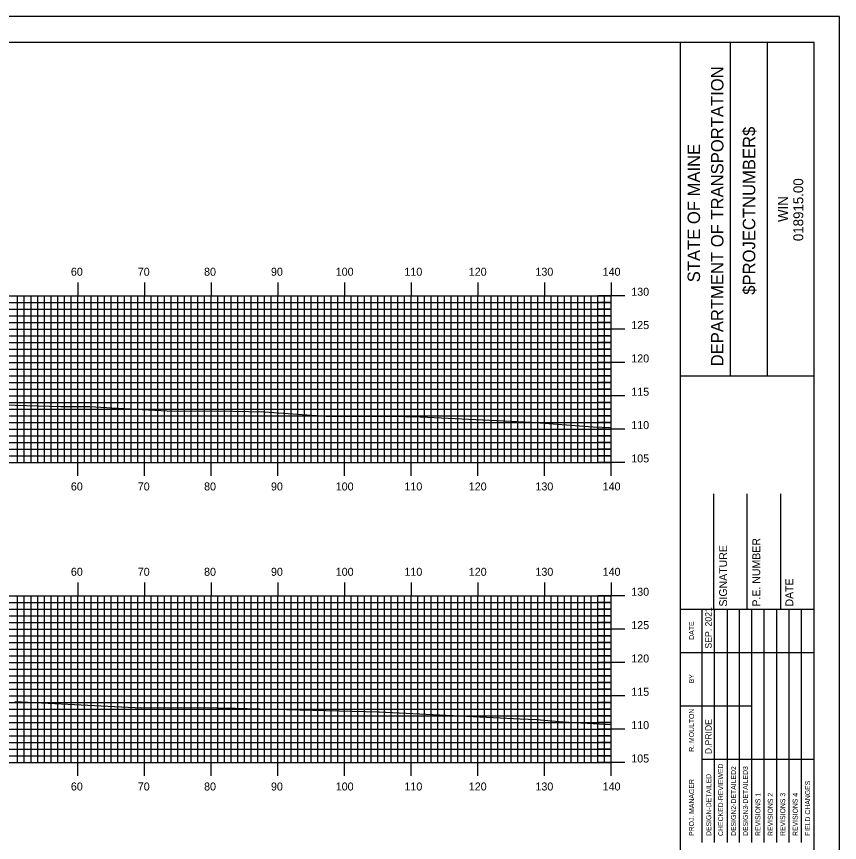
# Model space of a CAD drawing. Extents: x 1772022 to 1772366, y 442591 to 442811.
# Drawn here: x 1772238.9 to 1772362.3, y 442686.7 to 442810.5 of the extents above; entities that cross this region are included whole.
import ezdxf

# ---------------------------------------------------------------- set-up
doc = ezdxf.new("R2010")
doc.units = 0
for name, color, linetype in [('BORDER', 7, 'Continuous'), ('H_V ANNOTATION', 7, 'Continuous'), ('MAJOR', 7, 'Continuous'), ('MINOR', 7, 'Continuous'), ('PLOT BOUNDARY', 7, 'Continuous'), ('S_Roadway_Centerline', 7, 'Continuous')]:
    doc.layers.add(name, color=color, linetype=linetype)

msp = doc.modelspace()

# ---------------------------------------------------------------- linework, layer by layer
at = {"layer": 'BORDER'}
for p, q in [((1772338.49, 442596.67), (1772338.49, 442806.67)), ((1772345.95, 442756.66), (1772345.95, 442806.66)), ((1772351.54, 442756.66), (1772351.54, 442806.66)), ((1772338.5, 442756.65), (1772358.49, 442756.65)), ((1772343.49, 442721.67), (1772343.49, 442738.97)), ((1772348.49, 442721.67), (1772348.49, 442738.97)), ((1772353.49, 442721.67), (1772353.49, 442738.97)), ((1772338.49, 442721.67), (1772358.49, 442721.67))]:
    msp.add_line(p, q, dxfattribs=at)
msp.add_lwpolyline([(1772038.49, 442596.67), (1772358.49, 442596.67), (1772358.49, 442806.67), (1772038.49, 442806.67)], close=True, dxfattribs=at)
for points in [[(1772341.72, 442715.17), (1772341.72, 442721.67)], [(1772343.59, 442686.68), (1772343.59, 442721.67)], [(1772345.45, 442721.67), (1772345.45, 442686.68)], [(1772347.32, 442686.68), (1772347.32, 442721.67)], [(1772349.18, 442686.68), (1772349.18, 442721.67)], [(1772351.04, 442686.68), (1772351.04, 442721.67)], [(1772352.91, 442686.68), (1772352.91, 442721.67)], [(1772354.77, 442686.68), (1772354.77, 442721.67)], [(1772356.63, 442686.68), (1772356.63, 442721.67)], [(1772341.73, 442686.68), (1772341.73, 442720.26)], [(1772338.49, 442715.17), (1772358.49, 442715.17)], [(1772338.49, 442707.17), (1772341.73, 442707.17)], [(1772341.72, 442707.17), (1772349.18, 442707.17)], [(1772341.72, 442699.17), (1772358.49, 442699.17)]]:
    msp.add_lwpolyline(points, dxfattribs=at)
at = {"layer": 'MAJOR'}
for p, q in [((1772248.09, 442770.67), (1772248.09, 442768.67)), ((1772258.09, 442770.67), (1772258.09, 442768.67)), ((1772268.09, 442770.67), (1772268.09, 442768.67)), ((1772278.09, 442770.67), (1772278.09, 442768.67)), ((1772288.09, 442770.67), (1772288.09, 442768.67)), ((1772298.09, 442770.67), (1772298.09, 442768.67)), ((1772308.09, 442770.67), (1772308.09, 442768.67)), ((1772318.09, 442770.67), (1772318.09, 442768.67)), ((1772328.09, 442770.67), (1772328.09, 442768.67)), ((1772048.09, 442768.67), (1772328.09, 442768.67)), ((1772048.09, 442768.67), (1772328.09, 442768.67)), ((1772248.09, 442743.67), (1772248.09, 442768.67)), ((1772258.09, 442743.67), (1772258.09, 442768.67)), ((1772268.09, 442743.67), (1772268.09, 442768.67)), ((1772278.09, 442743.67), (1772278.09, 442768.67)), ((1772288.09, 442743.67), (1772288.09, 442768.67)), ((1772298.09, 442743.67), (1772298.09, 442768.67)), ((1772308.09, 442743.67), (1772308.09, 442768.67)), ((1772318.09, 442743.67), (1772318.09, 442768.67)), ((1772330.1, 442768.67), (1772326.09, 442768.67)), ((1772328.09, 442743.67), (1772328.09, 442768.67)), ((1772328.09, 442743.67), (1772328.09, 442768.67)), ((1772048.09, 442763.67), (1772328.09, 442763.67)), ((1772330.1, 442763.67), (1772326.09, 442763.67)), ((1772048.09, 442758.67), (1772328.09, 442758.67)), ((1772330.1, 442758.67), (1772326.09, 442758.67)), ((1772048.09, 442753.67), (1772328.09, 442753.67)), ((1772330.1, 442753.67), (1772326.09, 442753.67)), ((1772048.09, 442748.67), (1772328.09, 442748.67)), ((1772330.1, 442748.67), (1772326.09, 442748.67)), ((1772048.09, 442743.67), (1772328.09, 442743.67)), ((1772048.09, 442743.67), (1772328.09, 442743.67)), ((1772248.09, 442741.66), (1772248.09, 442743.67)), ((1772258.09, 442741.66), (1772258.09, 442743.67)), ((1772268.09, 442741.66), (1772268.09, 442743.67)), ((1772278.09, 442741.66), (1772278.09, 442743.67)), ((1772288.09, 442741.66), (1772288.09, 442743.67)), ((1772298.09, 442741.66), (1772298.09, 442743.67)), ((1772308.09, 442741.66), (1772308.09, 442743.67)), ((1772318.09, 442741.66), (1772318.09, 442743.67)), ((1772330.1, 442743.67), (1772326.09, 442743.67)), ((1772328.09, 442741.66), (1772328.09, 442743.67)), ((1772248.09, 442725.67), (1772248.09, 442723.67)), ((1772258.09, 442725.67), (1772258.09, 442723.67)), ((1772268.09, 442725.67), (1772268.09, 442723.67)), ((1772278.09, 442725.67), (1772278.09, 442723.67)), ((1772288.09, 442725.67), (1772288.09, 442723.67)), ((1772298.09, 442725.67), (1772298.09, 442723.67)), ((1772308.09, 442725.67), (1772308.09, 442723.67)), ((1772318.09, 442725.67), (1772318.09, 442723.67)), ((1772328.09, 442725.67), (1772328.09, 442723.67)), ((1772048.09, 442723.67), (1772328.09, 442723.67)), ((1772048.09, 442723.67), (1772328.09, 442723.67)), ((1772248.09, 442698.67), (1772248.09, 442723.67)), ((1772258.09, 442698.67), (1772258.09, 442723.67)), ((1772268.09, 442698.67), (1772268.09, 442723.67)), ((1772278.09, 442698.67), (1772278.09, 442723.67)), ((1772288.09, 442698.67), (1772288.09, 442723.67)), ((1772298.09, 442698.67), (1772298.09, 442723.67)), ((1772308.09, 442698.67), (1772308.09, 442723.67)), ((1772318.09, 442698.67), (1772318.09, 442723.67)), ((1772330.1, 442723.67), (1772326.09, 442723.67)), ((1772328.09, 442698.67), (1772328.09, 442723.67)), ((1772328.09, 442698.67), (1772328.09, 442723.67)), ((1772048.09, 442718.67), (1772328.09, 442718.67)), ((1772330.1, 442718.67), (1772326.09, 442718.67)), ((1772048.09, 442713.67), (1772328.09, 442713.67)), ((1772330.1, 442713.67), (1772326.09, 442713.67)), ((1772048.09, 442708.67), (1772328.09, 442708.67)), ((1772330.1, 442708.67), (1772326.09, 442708.67)), ((1772048.09, 442703.67), (1772328.09, 442703.67)), ((1772330.1, 442703.67), (1772326.09, 442703.67)), ((1772048.09, 442698.67), (1772328.09, 442698.67)), ((1772048.09, 442698.67), (1772328.09, 442698.67)), ((1772248.09, 442696.66), (1772248.09, 442698.67)), ((1772258.09, 442696.66), (1772258.09, 442698.67)), ((1772268.09, 442696.66), (1772268.09, 442698.67)), ((1772278.09, 442696.66), (1772278.09, 442698.67)), ((1772288.09, 442696.66), (1772288.09, 442698.67)), ((1772298.09, 442696.66), (1772298.09, 442698.67)), ((1772308.09, 442696.66), (1772308.09, 442698.67)), ((1772318.09, 442696.66), (1772318.09, 442698.67)), ((1772330.1, 442698.67), (1772326.09, 442698.67)), ((1772328.09, 442696.66), (1772328.09, 442698.67))]:
    msp.add_line(p, q, dxfattribs=at)
at = {"layer": 'MINOR'}
for p, q in [((1772239.09, 442743.67), (1772239.09, 442768.67)), ((1772240.09, 442743.67), (1772240.09, 442768.67)), ((1772241.09, 442743.67), (1772241.09, 442768.67)), ((1772242.09, 442743.67), (1772242.09, 442768.67)), ((1772243.09, 442743.67), (1772243.09, 442768.67)), ((1772244.09, 442743.67), (1772244.09, 442768.67)), ((1772245.09, 442743.67), (1772245.09, 442768.67)), ((1772246.09, 442743.67), (1772246.09, 442768.67)), ((1772247.09, 442743.67), (1772247.09, 442768.67)), ((1772249.09, 442743.67), (1772249.09, 442768.67)), ((1772250.09, 442743.67), (1772250.09, 442768.67)), ((1772251.09, 442743.67), (1772251.09, 442768.67)), ((1772252.09, 442743.67), (1772252.09, 442768.67)), ((1772253.09, 442743.67), (1772253.09, 442768.67)), ((1772254.09, 442743.67), (1772254.09, 442768.67)), ((1772255.09, 442743.67), (1772255.09, 442768.67)), ((1772256.09, 442743.67), (1772256.09, 442768.67)), ((1772257.09, 442743.67), (1772257.09, 442768.67)), ((1772259.09, 442743.67), (1772259.09, 442768.67)), ((1772260.09, 442743.67), (1772260.09, 442768.67)), ((1772261.09, 442743.67), (1772261.09, 442768.67)), ((1772262.09, 442743.67), (1772262.09, 442768.67)), ((1772263.09, 442743.67), (1772263.09, 442768.67)), ((1772264.09, 442743.67), (1772264.09, 442768.67)), ((1772265.09, 442743.67), (1772265.09, 442768.67)), ((1772266.09, 442743.67), (1772266.09, 442768.67)), ((1772267.09, 442743.67), (1772267.09, 442768.67)), ((1772269.09, 442743.67), (1772269.09, 442768.67)), ((1772270.09, 442743.67), (1772270.09, 442768.67)), ((1772271.09, 442743.67), (1772271.09, 442768.67)), ((1772272.09, 442743.67), (1772272.09, 442768.67)), ((1772273.09, 442743.67), (1772273.09, 442768.67)), ((1772274.09, 442743.67), (1772274.09, 442768.67)), ((1772275.09, 442743.67), (1772275.09, 442768.67)), ((1772276.09, 442743.67), (1772276.09, 442768.67)), ((1772277.09, 442743.67), (1772277.09, 442768.67)), ((1772279.09, 442743.67), (1772279.09, 442768.67)), ((1772280.09, 442743.67), (1772280.09, 442768.67)), ((1772281.09, 442743.67), (1772281.09, 442768.67)), ((1772282.09, 442743.67), (1772282.09, 442768.67)), ((1772283.09, 442743.67), (1772283.09, 442768.67)), ((1772284.09, 442743.67), (1772284.09, 442768.67)), ((1772285.09, 442743.67), (1772285.09, 442768.67)), ((1772286.09, 442743.67), (1772286.09, 442768.67)), ((1772287.09, 442743.67), (1772287.09, 442768.67)), ((1772289.09, 442743.67), (1772289.09, 442768.67)), ((1772290.09, 442743.67), (1772290.09, 442768.67)), ((1772291.09, 442743.67), (1772291.09, 442768.67)), ((1772292.09, 442743.67), (1772292.09, 442768.67)), ((1772293.09, 442743.67), (1772293.09, 442768.67)), ((1772294.09, 442743.67), (1772294.09, 442768.67)), ((1772295.09, 442743.67), (1772295.09, 442768.67)), ((1772296.09, 442743.67), (1772296.09, 442768.67)), ((1772297.09, 442743.67), (1772297.09, 442768.67)), ((1772299.09, 442743.67), (1772299.09, 442768.67)), ((1772300.09, 442743.67), (1772300.09, 442768.67)), ((1772301.09, 442743.67), (1772301.09, 442768.67)), ((1772302.09, 442743.67), (1772302.09, 442768.67)), ((1772303.09, 442743.67), (1772303.09, 442768.67)), ((1772304.09, 442743.67), (1772304.09, 442768.67)), ((1772305.09, 442743.67), (1772305.09, 442768.67)), ((1772306.09, 442743.67), (1772306.09, 442768.67)), ((1772307.09, 442743.67), (1772307.09, 442768.67)), ((1772309.09, 442743.67), (1772309.09, 442768.67)), ((1772310.09, 442743.67), (1772310.09, 442768.67)), ((1772311.09, 442743.67), (1772311.09, 442768.67)), ((1772312.09, 442743.67), (1772312.09, 442768.67)), ((1772313.09, 442743.67), (1772313.09, 442768.67)), ((1772314.09, 442743.67), (1772314.09, 442768.67)), ((1772315.09, 442743.67), (1772315.09, 442768.67)), ((1772316.09, 442743.67), (1772316.09, 442768.67)), ((1772317.09, 442743.67), (1772317.09, 442768.67)), ((1772319.09, 442743.67), (1772319.09, 442768.67)), ((1772320.09, 442743.67), (1772320.09, 442768.67)), ((1772321.09, 442743.67), (1772321.09, 442768.67)), ((1772322.09, 442743.67), (1772322.09, 442768.67)), ((1772323.09, 442743.67), (1772323.09, 442768.67)), ((1772324.09, 442743.67), (1772324.09, 442768.67)), ((1772325.09, 442743.67), (1772325.09, 442768.67)), ((1772326.09, 442743.67), (1772326.09, 442768.67)), ((1772327.09, 442743.67), (1772327.09, 442768.67)), ((1772048.09, 442767.67), (1772328.09, 442767.67)), ((1772328.09, 442767.67), (1772326.09, 442767.67)), ((1772048.09, 442766.67), (1772328.09, 442766.67)), ((1772328.09, 442766.67), (1772326.09, 442766.67)), ((1772048.09, 442765.67), (1772328.09, 442765.67)), ((1772328.09, 442765.67), (1772326.09, 442765.67)), ((1772048.09, 442764.67), (1772328.09, 442764.67)), ((1772328.09, 442764.67), (1772326.09, 442764.67)), ((1772048.09, 442762.67), (1772328.09, 442762.67)), ((1772328.09, 442762.67), (1772326.09, 442762.67)), ((1772048.09, 442761.67), (1772328.09, 442761.67)), ((1772328.09, 442761.67), (1772326.09, 442761.67)), ((1772048.09, 442760.67), (1772328.09, 442760.67)), ((1772328.09, 442760.67), (1772326.09, 442760.67)), ((1772048.09, 442759.67), (1772328.09, 442759.67)), ((1772328.09, 442759.67), (1772326.09, 442759.67)), ((1772048.09, 442757.67), (1772328.09, 442757.67)), ((1772328.09, 442757.67), (1772326.09, 442757.67)), ((1772048.09, 442756.67), (1772328.09, 442756.67)), ((1772328.09, 442756.67), (1772326.09, 442756.67)), ((1772048.09, 442755.67), (1772328.09, 442755.67)), ((1772328.09, 442755.67), (1772326.09, 442755.67)), ((1772048.09, 442754.67), (1772328.09, 442754.67)), ((1772328.09, 442754.67), (1772326.09, 442754.67)), ((1772048.09, 442752.67), (1772328.09, 442752.67)), ((1772328.09, 442752.67), (1772326.09, 442752.67)), ((1772048.09, 442751.67), (1772328.09, 442751.67)), ((1772328.09, 442751.67), (1772326.09, 442751.67)), ((1772048.09, 442750.67), (1772328.09, 442750.67)), ((1772328.09, 442750.67), (1772326.09, 442750.67)), ((1772048.09, 442749.67), (1772328.09, 442749.67)), ((1772328.09, 442749.67), (1772326.09, 442749.67)), ((1772048.09, 442747.67), (1772328.09, 442747.67)), ((1772328.09, 442747.67), (1772326.09, 442747.67)), ((1772048.09, 442746.67), (1772328.09, 442746.67)), ((1772328.09, 442746.67), (1772326.09, 442746.67)), ((1772048.09, 442745.67), (1772328.09, 442745.67)), ((1772328.09, 442745.67), (1772326.09, 442745.67)), ((1772048.09, 442744.67), (1772328.09, 442744.67)), ((1772328.09, 442744.67), (1772326.09, 442744.67)), ((1772239.09, 442698.67), (1772239.09, 442723.67)), ((1772240.09, 442698.67), (1772240.09, 442723.67)), ((1772241.09, 442698.67), (1772241.09, 442723.67)), ((1772242.09, 442698.67), (1772242.09, 442723.67)), ((1772243.09, 442698.67), (1772243.09, 442723.67)), ((1772244.09, 442698.67), (1772244.09, 442723.67)), ((1772245.09, 442698.67), (1772245.09, 442723.67)), ((1772246.09, 442698.67), (1772246.09, 442723.67)), ((1772247.09, 442698.67), (1772247.09, 442723.67)), ((1772249.09, 442698.67), (1772249.09, 442723.67)), ((1772250.09, 442698.67), (1772250.09, 442723.67)), ((1772251.09, 442698.67), (1772251.09, 442723.67)), ((1772252.09, 442698.67), (1772252.09, 442723.67)), ((1772253.09, 442698.67), (1772253.09, 442723.67)), ((1772254.09, 442698.67), (1772254.09, 442723.67)), ((1772255.09, 442698.67), (1772255.09, 442723.67)), ((1772256.09, 442698.67), (1772256.09, 442723.67)), ((1772257.09, 442698.67), (1772257.09, 442723.67)), ((1772259.09, 442698.67), (1772259.09, 442723.67)), ((1772260.09, 442698.67), (1772260.09, 442723.67)), ((1772261.09, 442698.67), (1772261.09, 442723.67)), ((1772262.09, 442698.67), (1772262.09, 442723.67)), ((1772263.09, 442698.67), (1772263.09, 442723.67)), ((1772264.09, 442698.67), (1772264.09, 442723.67)), ((1772265.09, 442698.67), (1772265.09, 442723.67)), ((1772266.09, 442698.67), (1772266.09, 442723.67)), ((1772267.09, 442698.67), (1772267.09, 442723.67)), ((1772269.09, 442698.67), (1772269.09, 442723.67)), ((1772270.09, 442698.67), (1772270.09, 442723.67)), ((1772271.09, 442698.67), (1772271.09, 442723.67)), ((1772272.09, 442698.67), (1772272.09, 442723.67)), ((1772273.09, 442698.67), (1772273.09, 442723.67)), ((1772274.09, 442698.67), (1772274.09, 442723.67)), ((1772275.09, 442698.67), (1772275.09, 442723.67)), ((1772276.09, 442698.67), (1772276.09, 442723.67)), ((1772277.09, 442698.67), (1772277.09, 442723.67)), ((1772279.09, 442698.67), (1772279.09, 442723.67)), ((1772280.09, 442698.67), (1772280.09, 442723.67)), ((1772281.09, 442698.67), (1772281.09, 442723.67)), ((1772282.09, 442698.67), (1772282.09, 442723.67)), ((1772283.09, 442698.67), (1772283.09, 442723.67)), ((1772284.09, 442698.67), (1772284.09, 442723.67)), ((1772285.09, 442698.67), (1772285.09, 442723.67)), ((1772286.09, 442698.67), (1772286.09, 442723.67)), ((1772287.09, 442698.67), (1772287.09, 442723.67)), ((1772289.09, 442698.67), (1772289.09, 442723.67)), ((1772290.09, 442698.67), (1772290.09, 442723.67)), ((1772291.09, 442698.67), (1772291.09, 442723.67)), ((1772292.09, 442698.67), (1772292.09, 442723.67)), ((1772293.09, 442698.67), (1772293.09, 442723.67)), ((1772294.09, 442698.67), (1772294.09, 442723.67)), ((1772295.09, 442698.67), (1772295.09, 442723.67)), ((1772296.09, 442698.67), (1772296.09, 442723.67)), ((1772297.09, 442698.67), (1772297.09, 442723.67)), ((1772299.09, 442698.67), (1772299.09, 442723.67)), ((1772300.09, 442698.67), (1772300.09, 442723.67)), ((1772301.09, 442698.67), (1772301.09, 442723.67)), ((1772302.09, 442698.67), (1772302.09, 442723.67)), ((1772303.09, 442698.67), (1772303.09, 442723.67)), ((1772304.09, 442698.67), (1772304.09, 442723.67)), ((1772305.09, 442698.67), (1772305.09, 442723.67)), ((1772306.09, 442698.67), (1772306.09, 442723.67)), ((1772307.09, 442698.67), (1772307.09, 442723.67)), ((1772309.09, 442698.67), (1772309.09, 442723.67)), ((1772310.09, 442698.67), (1772310.09, 442723.67)), ((1772311.09, 442698.67), (1772311.09, 442723.67)), ((1772312.09, 442698.67), (1772312.09, 442723.67)), ((1772313.09, 442698.67), (1772313.09, 442723.67)), ((1772314.09, 442698.67), (1772314.09, 442723.67)), ((1772315.09, 442698.67), (1772315.09, 442723.67)), ((1772316.09, 442698.67), (1772316.09, 442723.67)), ((1772317.09, 442698.67), (1772317.09, 442723.67)), ((1772319.09, 442698.67), (1772319.09, 442723.67)), ((1772320.09, 442698.67), (1772320.09, 442723.67)), ((1772321.09, 442698.67), (1772321.09, 442723.67)), ((1772322.09, 442698.67), (1772322.09, 442723.67)), ((1772323.09, 442698.67), (1772323.09, 442723.67)), ((1772324.09, 442698.67), (1772324.09, 442723.67)), ((1772325.09, 442698.67), (1772325.09, 442723.67)), ((1772326.09, 442698.67), (1772326.09, 442723.67)), ((1772327.09, 442698.67), (1772327.09, 442723.67)), ((1772048.09, 442722.67), (1772328.09, 442722.67)), ((1772048.09, 442721.67), (1772328.09, 442721.67)), ((1772328.09, 442722.67), (1772326.09, 442722.67)), ((1772328.09, 442721.67), (1772326.09, 442721.67)), ((1772048.09, 442720.67), (1772328.09, 442720.67)), ((1772328.09, 442720.67), (1772326.09, 442720.67)), ((1772048.09, 442719.67), (1772328.09, 442719.67)), ((1772328.09, 442719.67), (1772326.09, 442719.67)), ((1772048.09, 442717.67), (1772328.09, 442717.67)), ((1772048.09, 442716.67), (1772328.09, 442716.67)), ((1772328.09, 442717.67), (1772326.09, 442717.67)), ((1772328.09, 442716.67), (1772326.09, 442716.67)), ((1772048.09, 442715.67), (1772328.09, 442715.67)), ((1772328.09, 442715.67), (1772326.09, 442715.67)), ((1772048.09, 442714.67), (1772328.09, 442714.67)), ((1772328.09, 442714.67), (1772326.09, 442714.67)), ((1772048.09, 442712.67), (1772328.09, 442712.67)), ((1772048.09, 442711.67), (1772328.09, 442711.67)), ((1772328.09, 442712.67), (1772326.09, 442712.67)), ((1772328.09, 442711.67), (1772326.09, 442711.67)), ((1772048.09, 442710.67), (1772328.09, 442710.67)), ((1772328.09, 442710.67), (1772326.09, 442710.67)), ((1772048.09, 442709.67), (1772328.09, 442709.67)), ((1772328.09, 442709.67), (1772326.09, 442709.67)), ((1772048.09, 442707.67), (1772328.09, 442707.67)), ((1772048.09, 442706.67), (1772328.09, 442706.67)), ((1772328.09, 442707.67), (1772326.09, 442707.67)), ((1772328.09, 442706.67), (1772326.09, 442706.67)), ((1772048.09, 442705.67), (1772328.09, 442705.67)), ((1772328.09, 442705.67), (1772326.09, 442705.67)), ((1772048.09, 442704.67), (1772328.09, 442704.67)), ((1772328.09, 442704.67), (1772326.09, 442704.67)), ((1772048.09, 442702.67), (1772328.09, 442702.67)), ((1772048.09, 442701.67), (1772328.09, 442701.67)), ((1772328.09, 442702.67), (1772326.09, 442702.67)), ((1772328.09, 442701.67), (1772326.09, 442701.67)), ((1772048.09, 442700.67), (1772328.09, 442700.67)), ((1772328.09, 442700.67), (1772326.09, 442700.67)), ((1772048.09, 442699.67), (1772328.09, 442699.67)), ((1772328.09, 442699.67), (1772326.09, 442699.67))]:
    msp.add_line(p, q, dxfattribs=at)
at = {"layer": 'PLOT BOUNDARY'}
msp.add_lwpolyline([(1772022.31, 442590.55), (1772362.31, 442590.55), (1772362.31, 442810.55), (1772022.31, 442810.55)], close=True, dxfattribs=at)
at = {"layer": 'S_Roadway_Centerline'}
for points in [[(1772233.53, 442752.41), (1772245.56, 442752.05), (1772249.9, 442752.08), (1772254.06, 442751.82), (1772261.53, 442751.42), (1772271.36, 442751.35), (1772276.11, 442751.24), (1772285.3, 442750.63), (1772295.07, 442750.62), (1772299.5, 442750.5), (1772316.06, 442749.71), (1772325.32, 442749.02), (1772328.09, 442748.89)], [(1772238.68, 442707.82), (1772252.59, 442707.13), (1772257.72, 442706.89), (1772266.16, 442706.92), (1772271.73, 442706.82), (1772273.48, 442706.78), (1772293.2, 442706.28), (1772293.27, 442706.28), (1772293.28, 442706.28), (1772293.29, 442706.28), (1772314.43, 442705.2), (1772316.94, 442705.14), (1772320.84, 442704.79), (1772328.09, 442704.36)]]:
    msp.add_lwpolyline(points, dxfattribs=at)

# ---------------------------------------------------------------- texts
at = {"layer": 'BORDER'}
for s, height, p in [('DEPARTMENT OF TRANSPORTATION', 1.8635, (1772344.91, 442758.08)), ('$PROJECTNUMBER$', 1.8635, (1772349.68, 442768.82)), ('STATE OF MAINE', 1.8635, (1772341.4, 442770.69)), ('018915.00', 1.491, (1772356.88, 442776.86)), ('WIN', 1.491, (1772354.57, 442779.73)), ('P.E. NUMBER', 1.1811, (1772350.42, 442722.06)), ('SIGNATURE', 1.181, (1772345.45, 442722.06)), ('DATE', 1.181, (1772355.38, 442722.06)), ('SEP. 2021', 0.969, (1772343.14, 442715.76)), ('DATE', 0.743, (1772340.5, 442717.08)), ('BY', 0.743, (1772340.5, 442710.54)), ('R. MOULTON', 0.745, (1772340.5, 442700.28)), ('D.PRIDE', 0.969, (1772343.14, 442699.92)), ('CHECKED-REVIEWED', 0.7455, (1772344.86, 442687.65)), ('DESIGN2-DETAILED2', 0.7455, (1772346.79, 442687.65)), ('DESIGN3-DETAILED3', 0.7455, (1772348.58, 442687.65)), ('PROJ. MANAGER', 0.7455, (1772340.5, 442687.65)), ('DESIGN-DETAILED', 0.7455, (1772343.07, 442687.65)), ('FIELD CHANGES', 0.7455, (1772357.9, 442687.65)), ('REVISIONS 1', 0.7455, (1772350.45, 442687.65)), ('REVISIONS 2', 0.7455, (1772352.31, 442687.65)), ('REVISIONS 3', 0.7455, (1772354.17, 442687.65)), ('REVISIONS 4', 0.7455, (1772356.04, 442687.65))]:
    msp.add_text(s, height=height, rotation=90, dxfattribs=at).set_placement(p)
at = {"layer": 'H_V ANNOTATION'}
for s, p in [('60', (1772247.07, 442771.67)), ('70', (1772257.1, 442771.67)), ('80', (1772267.04, 442771.67)), ('90', (1772277.07, 442771.67)), ('100', (1772286.78, 442771.67)), ('110', (1772297.08, 442771.67)), ('120', (1772306.73, 442771.67)), ('130', (1772316.72, 442771.67)), ('140', (1772326.8, 442771.67)), ('130', (1772331.09, 442768.67)), ('125', (1772331.09, 442763.67)), ('120', (1772331.09, 442758.67)), ('115', (1772331.09, 442753.67)), ('110', (1772331.09, 442748.67)), ('105', (1772331.09, 442743.67)), ('60', (1772247.07, 442739.47)), ('70', (1772257.1, 442739.47)), ('80', (1772267.04, 442739.47)), ('90', (1772277.07, 442739.47)), ('100', (1772286.78, 442739.47)), ('110', (1772297.08, 442739.47)), ('120', (1772306.73, 442739.47)), ('130', (1772316.72, 442739.47)), ('140', (1772326.8, 442739.47)), ('60', (1772247.07, 442726.67)), ('70', (1772257.1, 442726.67)), ('80', (1772267.04, 442726.67)), ('90', (1772277.07, 442726.67)), ('100', (1772286.78, 442726.67)), ('110', (1772297.08, 442726.67)), ('120', (1772306.73, 442726.67)), ('130', (1772316.72, 442726.67)), ('140', (1772326.8, 442726.67)), ('130', (1772331.09, 442723.67)), ('125', (1772331.09, 442718.67)), ('120', (1772331.09, 442713.67)), ('115', (1772331.09, 442708.67)), ('110', (1772331.09, 442703.67)), ('105', (1772331.09, 442698.67)), ('60', (1772247.07, 442694.47)), ('70', (1772257.1, 442694.47)), ('80', (1772267.04, 442694.47)), ('90', (1772277.07, 442694.47)), ('100', (1772286.78, 442694.47)), ('110', (1772297.08, 442694.47)), ('120', (1772306.73, 442694.47)), ('130', (1772316.72, 442694.47)), ('140', (1772326.8, 442694.47))]:
    msp.add_text(s, height=1.2, dxfattribs=at).set_placement(p)

doc.saveas('drawing.dxf')
